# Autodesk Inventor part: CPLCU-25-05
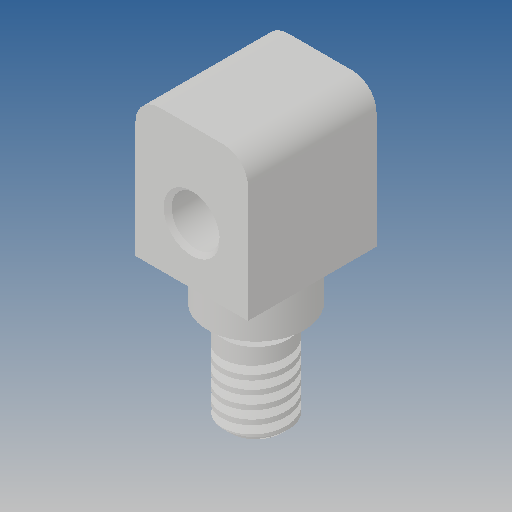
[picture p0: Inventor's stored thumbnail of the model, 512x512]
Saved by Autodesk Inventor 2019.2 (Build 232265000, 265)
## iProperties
Created: 2010-03
Part Number: CPLCU-25-05
Material: Ogólny
Document SubType Name: Modeling
Designer: CADENGINEERING4
Density: 1 g/cm^3
Appearance: Domyślna
Author: CADENGINEERING4
Revision Number: 2LAST_VERSION
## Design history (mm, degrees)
feature "Baza1"
node "Bryła1"
